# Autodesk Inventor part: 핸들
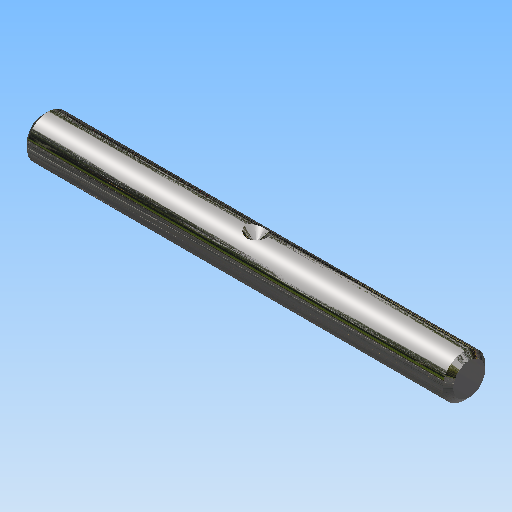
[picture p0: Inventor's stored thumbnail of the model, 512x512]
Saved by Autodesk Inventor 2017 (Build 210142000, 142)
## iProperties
Created: 2019-04
Part Number: 핸들
Material: 스테인리스강
Document SubType Name: Modeling
Designer: mduedu
Density: 1 g/cm^3
Appearance: 반광택
Author: mduedu
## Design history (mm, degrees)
sketch "스케치1"
  geometry: C1 r 4 at (0, 0); 1 further point
  constraints: 1 centre point, 1 coincident
  dimensions: "d0" = 8 diameter of C1
extrude "돌출1" new body sketch "스케치1" stored distance "d1" = 80; taper "d2" = 0 deg
chamfer "모따기1" distance "d3" = 1; stored, may be unused: second distance "d4" = 2, angle "d5" = 45 deg
sketch "스케치2"
  geometry: L1 (-39, 4)-(39, 4) reference; L2 (0, 4)-(0, 2); L3 (0, 2)-(2, 4); L4 (0, 4)-(2, 4); 1 further point
  constraints: 6 end point, 2 perpendicular, 1 midpoint, 1 point on line
  dimensions: "d6" = 4 diameter of L3.end L2; "d8" = 45 deg angle of L3 L2
revolve "회전1" sketch "스케치2" stored, may be unused: angle "d10" = 90 deg
node "작업점1"
  node "작업축1"
  node "작업 평면1"
node "솔리드1"
